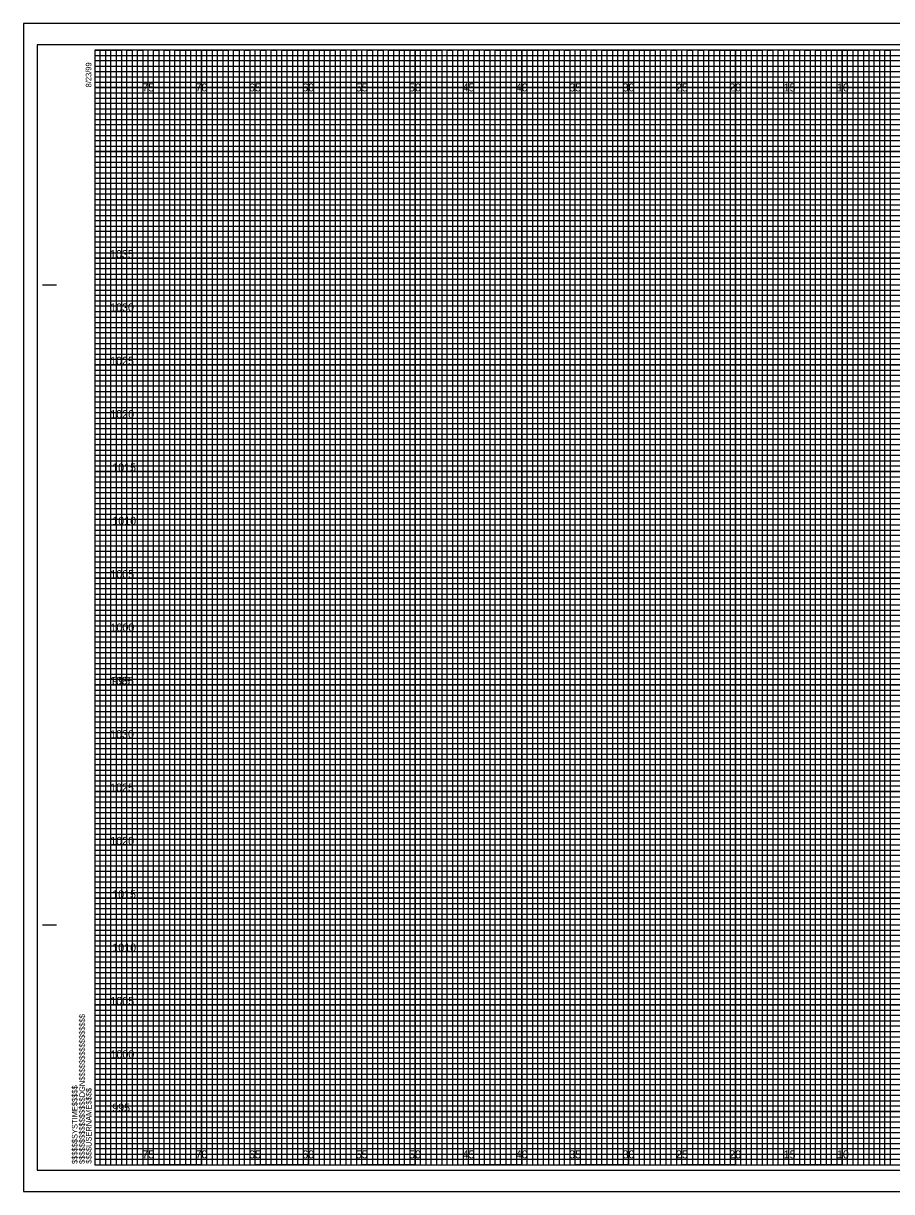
# Model space of a CAD drawing. Extents: x -7 to 162, y -2 to 987.
# Drawn here: x -6.7 to 74.6, y 437.5 to 547 of the extents above; entities that cross this region are included whole.
import ezdxf

# ---------------------------------------------------------------- set-up
doc = ezdxf.new("R2010")
doc.units = 0
for name, color, linetype in [('Exist Cross Section Cell', 7, 'Continuous'), ('Exist XS Center Line Elevation Label', 7, 'Continuous'), ('Exist XS Ground Line', 7, 'Continuous'), ('Prop CMT Concrete Structures', 7, 'Continuous'), ('Prop CMT Guardrail Widen Shoulder', 7, 'Continuous'), ('Prop CMT Pvmt Course 1', 7, 'Continuous'), ('Prop CMT Pvmt Surface', 7, 'Continuous'), ('Prop CMT Shld Paved Course 1', 7, 'Continuous'), ('Prop CMT Slope Grass', 7, 'Continuous'), ('Prop CMT Subgrade Earthwork', 7, 'Continuous'), ('Typical Text Label CELL', 7, 'Continuous')]:
    doc.layers.add(name, color=color, linetype=linetype)

msp = doc.modelspace()

# ---------------------------------------------------------------- linework, layer by layer
at = {"layer": 'Exist XS Center Line Elevation Label'}
for points in [[(0, 544.5), (2.5, 544.5), (2.5, 440), (7.5, 440), (7.5, 544.5), (12.5, 544.5), (12.5, 440), (17.5, 440), (17.5, 544.5), (22.5, 544.5), (22.5, 440), (27.5, 440), (27.5, 544.5), (32.5, 544.5), (32.5, 440), (37.5, 440), (37.5, 544.5), (42.5, 544.5), (42.5, 440), (47.5, 440), (47.5, 544.5), (52.5, 544.5), (52.5, 440), (57.5, 440), (57.5, 544.5), (62.5, 544.5), (62.5, 440), (67.5, 440), (67.5, 544.5), (72.5, 544.5), (72.5, 440), (77.5, 440)], [(0, 542), (137.5, 542)], [(0, 532.5), (160, 532.5), (160, 537.5), (0, 537.5)], [(0, 522.5), (160, 522.5), (160, 527.5), (0, 527.5)], [(0, 512.5), (160, 512.5), (160, 517.5), (0, 517.5)], [(0, 502.5), (160, 502.5), (160, 507.5), (0, 507.5)], [(0, 492.5), (160, 492.5), (160, 497.5), (0, 497.5)], [(0, 482.5), (160, 482.5), (160, 487.5), (0, 487.5)], [(0, 472.5), (160, 472.5), (160, 477.5), (0, 477.5)], [(0, 462.5), (160, 462.5), (160, 467.5), (0, 467.5)], [(0, 452.5), (160, 452.5), (160, 457.5), (0, 457.5)], [(0, 442.5), (160, 442.5), (160, 447.5), (0, 447.5)]]:
    msp.add_lwpolyline(points, dxfattribs=at)
at = {"layer": 'Exist XS Ground Line'}
for p, q in [((5, 544.5), (0, 544.5)), ((5, 440), (5, 544.5)), ((15, 544.5), (10, 544.5)), ((10, 544.5), (10, 440)), ((15, 440), (15, 544.5)), ((25, 544.5), (20, 544.5)), ((20, 544.5), (20, 440)), ((25, 440), (25, 544.5)), ((35, 544.5), (30, 544.5)), ((30, 544.5), (30, 440)), ((35, 440), (35, 544.5)), ((45, 544.5), (40, 544.5)), ((40, 544.5), (40, 440)), ((45, 440), (45, 544.5)), ((55, 544.5), (50, 544.5)), ((50, 544.5), (50, 440)), ((55, 440), (55, 544.5)), ((65, 544.5), (60, 544.5)), ((60, 544.5), (60, 440)), ((65, 440), (65, 544.5)), ((75, 544.5), (70, 544.5)), ((70, 544.5), (70, 440)), ((10, 440), (5, 440)), ((20, 440), (15, 440)), ((30, 440), (25, 440)), ((40, 440), (35, 440)), ((50, 440), (45, 440)), ((60, 440), (55, 440)), ((70, 440), (65, 440))]:
    msp.add_line(p, q, dxfattribs=at)
for points in [[(0, 540), (160, 540), (160, 535), (0, 535)], [(0, 530), (160, 530), (160, 525), (0, 525)], [(0, 520), (160, 520), (160, 515), (0, 515)], [(0, 510), (160, 510), (160, 505), (0, 505)], [(0, 500), (160, 500), (160, 495), (0, 495)], [(0, 490), (160, 490), (160, 485), (0, 485)], [(0, 480), (160, 480), (160, 475), (0, 475)], [(0, 470), (160, 470), (160, 465), (0, 465)], [(0, 460), (160, 460), (160, 455), (0, 455)], [(0, 450), (160, 450), (160, 445), (0, 445)]]:
    msp.add_lwpolyline(points, dxfattribs=at)
at = {"layer": 'Prop CMT Concrete Structures'}
for p, q in [((5, 440), (5, 544.5)), ((10, 440), (10, 544.5)), ((15, 440), (15, 544.5)), ((20, 440), (20, 544.5)), ((25, 440), (25, 544.5)), ((30, 440), (30, 544.5)), ((35, 440), (35, 544.5)), ((40, 440), (40, 544.5)), ((45, 440), (45, 544.5)), ((50, 440), (50, 544.5)), ((55, 440), (55, 544.5)), ((60, 440), (60, 544.5)), ((65, 440), (65, 544.5)), ((70, 440), (70, 544.5)), ((0, 540), (160, 540)), ((0, 535), (160, 535)), ((0, 530), (160, 530)), ((0, 525), (160, 525)), ((0, 520), (160, 520)), ((0, 515), (160, 515)), ((0, 510), (160, 510)), ((0, 505), (160, 505)), ((0, 500), (160, 500)), ((0, 495), (160, 495)), ((0, 490), (160, 490)), ((0, 485), (160, 485)), ((0, 480), (160, 480)), ((0, 475), (160, 475)), ((0, 470), (160, 470)), ((0, 465), (160, 465)), ((0, 460), (160, 460)), ((0, 455), (160, 455)), ((0, 450), (160, 450)), ((0, 445), (160, 445))]:
    msp.add_line(p, q, dxfattribs=at)
at = {"layer": 'Prop CMT Guardrail Widen Shoulder'}
for p, q in [((161.65, 547), (-6.7, 547)), ((-6.7, 547), (-6.7, 437.5)), ((-6.7, 437.5), (161.65, 437.5))]:
    msp.add_line(p, q, dxfattribs=at)
at = {"layer": 'Prop CMT Pvmt Course 1'}
msp.add_lwpolyline([(-6.7, 437.5), (161.65, 437.5), (161.65, 547), (-6.7, 547)], close=True, dxfattribs=at)
at = {"layer": 'Prop CMT Pvmt Surface'}
for points in [[(0, 440), (0.5, 440), (0.5, 544.5), (1, 544.5), (1, 440)], [(1, 440), (1.5, 440), (1.5, 544.5), (2, 544.5), (2, 440)], [(2.5, 440), (3, 440), (3, 544.5), (3.5, 544.5), (3.5, 440)], [(3.5, 440), (4, 440), (4, 544.5), (4.5, 544.5), (4.5, 440)], [(5, 440), (5.5, 440), (5.5, 544.5), (6, 544.5), (6, 440)], [(6, 440), (6.5, 440), (6.5, 544.5), (7, 544.5), (7, 440)], [(7.5, 440), (8, 440), (8, 544.5), (8.5, 544.5), (8.5, 440)], [(8.5, 440), (9, 440), (9, 544.5), (9.5, 544.5), (9.5, 440)], [(10, 440), (10.5, 440), (10.5, 544.5), (11, 544.5), (11, 440)], [(11, 440), (11.5, 440), (11.5, 544.5), (12, 544.5), (12, 440)], [(12.5, 440), (13, 440), (13, 544.5), (13.5, 544.5), (13.5, 440)], [(13.5, 440), (14, 440), (14, 544.5), (14.5, 544.5), (14.5, 440)], [(15, 440), (15.5, 440), (15.5, 544.5), (16, 544.5), (16, 440)], [(16, 440), (16.5, 440), (16.5, 544.5), (17, 544.5), (17, 440)], [(17.5, 440), (18, 440), (18, 544.5), (18.5, 544.5), (18.5, 440)], [(18.5, 440), (19, 440), (19, 544.5), (19.5, 544.5), (19.5, 440)], [(20, 440), (20.5, 440), (20.5, 544.5), (21, 544.5), (21, 440)], [(21, 440), (21.5, 440), (21.5, 544.5), (22, 544.5), (22, 440)], [(22.5, 440), (23, 440), (23, 544.5), (23.5, 544.5), (23.5, 440)], [(23.5, 440), (24, 440), (24, 544.5), (24.5, 544.5), (24.5, 440)], [(25, 440), (25.5, 440), (25.5, 544.5), (26, 544.5), (26, 440)], [(26, 440), (26.5, 440), (26.5, 544.5), (27, 544.5), (27, 440)], [(27.5, 440), (28, 440), (28, 544.5), (28.5, 544.5), (28.5, 440)], [(28.5, 440), (29, 440), (29, 544.5), (29.5, 544.5), (29.5, 440)], [(30, 440), (30.5, 440), (30.5, 544.5), (31, 544.5), (31, 440)], [(31, 440), (31.5, 440), (31.5, 544.5), (32, 544.5), (32, 440)], [(32.5, 440), (33, 440), (33, 544.5), (33.5, 544.5), (33.5, 440)], [(33.5, 440), (34, 440), (34, 544.5), (34.5, 544.5), (34.5, 440)], [(35, 440), (35.5, 440), (35.5, 544.5), (36, 544.5), (36, 440)], [(36, 440), (36.5, 440), (36.5, 544.5), (37, 544.5), (37, 440)], [(37.5, 440), (38, 440), (38, 544.5), (38.5, 544.5), (38.5, 440)], [(38.5, 440), (39, 440), (39, 544.5), (39.5, 544.5), (39.5, 440)], [(40, 440), (40.5, 440), (40.5, 544.5), (41, 544.5), (41, 440)], [(41, 440), (41.5, 440), (41.5, 544.5), (42, 544.5), (42, 440)], [(42.5, 440), (43, 440), (43, 544.5), (43.5, 544.5), (43.5, 440)], [(43.5, 440), (44, 440), (44, 544.5), (44.5, 544.5), (44.5, 440)], [(45, 440), (45.5, 440), (45.5, 544.5), (46, 544.5), (46, 440)], [(46, 440), (46.5, 440), (46.5, 544.5), (47, 544.5), (47, 440)], [(47.5, 440), (48, 440), (48, 544.5), (48.5, 544.5), (48.5, 440)], [(48.5, 440), (49, 440), (49, 544.5), (49.5, 544.5), (49.5, 440)], [(50, 440), (50.5, 440), (50.5, 544.5), (51, 544.5), (51, 440)], [(51, 440), (51.5, 440), (51.5, 544.5), (52, 544.5), (52, 440)], [(52.5, 440), (53, 440), (53, 544.5), (53.5, 544.5), (53.5, 440)], [(53.5, 440), (54, 440), (54, 544.5), (54.5, 544.5), (54.5, 440)], [(55, 440), (55.5, 440), (55.5, 544.5), (56, 544.5), (56, 440)], [(56, 440), (56.5, 440), (56.5, 544.5), (57, 544.5), (57, 440)], [(57.5, 440), (58, 440), (58, 544.5), (58.5, 544.5), (58.5, 440)], [(58.5, 440), (59, 440), (59, 544.5), (59.5, 544.5), (59.5, 440)], [(60, 440), (60.5, 440), (60.5, 544.5), (61, 544.5), (61, 440)], [(61, 440), (61.5, 440), (61.5, 544.5), (62, 544.5), (62, 440)], [(62.5, 440), (63, 440), (63, 544.5), (63.5, 544.5), (63.5, 440)], [(63.5, 440), (64, 440), (64, 544.5), (64.5, 544.5), (64.5, 440)], [(65, 440), (65.5, 440), (65.5, 544.5), (66, 544.5), (66, 440)], [(66, 440), (66.5, 440), (66.5, 544.5), (67, 544.5), (67, 440)], [(67.5, 440), (68, 440), (68, 544.5), (68.5, 544.5), (68.5, 440)], [(68.5, 440), (69, 440), (69, 544.5), (69.5, 544.5), (69.5, 440)], [(70, 440), (70.5, 440), (70.5, 544.5), (71, 544.5), (71, 440)], [(71, 440), (71.5, 440), (71.5, 544.5), (72, 544.5), (72, 440)], [(72.5, 440), (73, 440), (73, 544.5), (73.5, 544.5), (73.5, 440)], [(73.5, 440), (74, 440), (74, 544.5), (74.5, 544.5), (74.5, 440)]]:
    msp.add_lwpolyline(points, dxfattribs=at)
at = {"layer": 'Prop CMT Shld Paved Course 1'}
for p, q in [((0, 544), (130, 544)), ((130, 543.49), (0, 543.49)), ((0, 543.49), (0, 543)), ((0, 543), (130, 543)), ((130, 542.45), (0, 542.45)), ((0, 542.45), (0, 541.5)), ((0, 541.5), (160, 541.5))]:
    msp.add_line(p, q, dxfattribs=at)
for points in [[(0, 541), (135, 541), (160, 541), (160, 541), (0, 541)], [(0, 540.5), (160, 540.5), (160, 539.5), (0, 539.5)], [(0, 539), (160, 539), (160, 538.5), (0, 538.49)], [(0, 538), (160, 538), (160, 537), (0, 537)], [(0, 536.5), (160, 536.5), (160, 536), (0, 536)], [(0, 535.5), (160, 535.5), (160, 534.5), (0, 534.5)], [(0, 534), (160, 534), (160, 533.5), (0, 533.5)], [(0, 533), (160, 533), (160, 532), (0, 532)], [(0, 531.5), (160, 531.5), (160, 531), (0, 531)], [(0, 530.5), (160, 530.5), (160, 529.5), (0, 529.5)], [(0, 529), (160, 529), (160, 528.5), (0, 528.5)], [(0, 528), (160, 528), (160, 526.98), (160, 526.5), (160, 526), (0, 526)], [(0, 527), (160, 527), (160, 526.5), (0, 526.5)], [(0, 525.5), (160, 525.5), (160, 524.5), (0, 524.51)], [(0, 524.51), (160, 524.5), (160, 524), (0, 524)], [(0, 523.5), (160, 523.5), (160, 523), (0, 523)], [(0, 522), (160, 522), (160, 521.5), (0, 521.5)], [(0, 521), (160, 521), (160, 520.5), (0, 520.5)], [(-0.04, 519.45), (160, 519.45), (160, 518.94), (-0.04, 518.94)], [(0, 518.5), (160, 518.5), (160, 518), (0, 518)], [(0, 517), (160, 517), (160, 516.5), (0, 516.5)], [(0, 516), (160, 516), (160, 515.5), (0, 515.5)], [(0, 514.5), (160, 514.5), (160, 514), (0, 514)], [(0, 513.5), (160, 513.5), (160, 513), (0, 513)], [(0, 512), (160, 512), (160, 511.5), (0, 511.5)], [(0, 511), (160, 511), (160, 510.5), (0, 510.5)], [(0, 509.5), (160, 509.5), (160, 508.99), (0, 509)], [(0, 508.5), (160, 508.5), (160, 508), (0, 508)], [(0, 507), (160, 507), (160, 506.5), (0, 506.5)], [(0, 506), (160, 506), (160, 505.5), (0, 505.5)], [(0, 504.5), (160, 504.5), (160, 504), (0, 504)], [(0, 503.5), (160, 503.5), (160, 503), (0, 503)], [(0, 502), (160, 502), (160, 501.5), (0, 501.5)], [(0, 501), (160, 501), (160, 500.5), (0, 500.5)], [(0, 499.5), (160, 499.5), (160, 499), (0, 499)], [(0, 498.5), (160.03, 498.45), (160, 498), (0, 498)], [(0, 497), (160, 497), (160, 496.5), (0, 496.5)], [(0, 496), (160, 496), (160, 495.5), (0, 495.5)], [(0, 494.5), (160, 494.5), (160, 494), (0, 494)], [(0, 493.5), (160, 493.5), (160, 493), (0, 493)], [(0, 492), (160, 492), (160, 491.5), (0, 491.5)], [(0, 491), (160, 491), (160, 490.5), (0, 490.5)], [(0, 489.5), (160, 489.5), (160, 489), (0, 489)], [(0, 488.5), (160, 488.5), (160, 488), (0, 488)], [(0, 487), (160, 487), (160, 486.5), (0, 486.5)], [(0, 486), (160, 486), (160, 485.5), (0, 485.5)], [(0, 484.5), (160, 484.5), (160, 484), (0, 484)], [(0, 483.5), (160, 483.5), (160, 483), (0, 483)], [(0, 482), (160, 482), (160, 481.5), (0, 481.5)], [(0, 481), (160, 481), (160, 480.5), (0, 480.5)], [(0, 479.5), (160, 479.5), (160, 478.99), (0, 479)], [(0, 478.5), (160, 478.5), (160, 478), (0, 478)], [(0, 477), (160, 477), (160, 476.5), (0, 476.5)], [(0, 476), (160, 476), (160, 475.5), (0, 475.5)], [(0, 474.5), (160, 474.5), (160, 474), (0, 474)], [(0, 473.5), (160, 473.5), (160, 473), (0, 473)], [(0, 472), (160, 472), (160, 471.5), (0, 471.5)], [(0, 471), (160, 471), (160, 470.5), (0, 470.5)], [(0, 469.5), (160, 469.5), (160, 469), (0, 469)], [(0, 468.5), (160.03, 468.45), (160, 468), (0, 468)], [(0, 467), (160, 467), (160, 466.5), (0, 466.5)], [(0, 466), (160, 466), (160, 465.5), (0, 465.5)], [(0, 464.5), (160, 464.5), (160, 464), (0, 464)], [(0, 463.5), (160, 463.5), (160, 463), (0, 463)], [(0, 462), (160, 462), (160, 461.5), (0, 461.5)], [(0, 461), (160, 461), (160, 460.5), (0, 460.5)], [(0, 459.5), (160, 459.5), (160, 459), (0, 459)], [(0, 458.5), (160, 458.5), (160, 458), (0, 458)], [(0, 457), (160, 457), (160, 456.5), (0, 456.5)], [(0, 456), (160, 456), (160, 455.5), (0, 455.5)], [(0, 454.5), (160, 454.5), (160, 454), (0, 454)], [(0, 453.5), (160, 453.5), (160, 453), (0, 453)], [(0, 452), (160, 452), (160, 451.5), (0, 451.5)], [(0, 451), (160, 451), (160, 450.5), (0, 450.5)], [(0, 449.5), (160, 449.5), (160, 449), (0, 449)], [(0, 448.5), (160, 448.5), (160, 448), (0, 448)], [(0, 447), (160, 447), (160, 446.5), (0, 446.5)], [(0, 446), (160, 446), (160, 445.5), (0, 445.5)], [(0, 444.5), (160, 444.5), (160, 444), (0, 444)], [(0, 443.5), (160, 443.5), (160, 443), (0, 443)], [(0, 442), (160, 442), (160, 441.5), (0, 441.5)], [(0, 441), (160, 441), (160, 440.5), (0, 440.5)]]:
    msp.add_lwpolyline(points, dxfattribs=at)
at = {"layer": 'Prop CMT Slope Grass'}
msp.add_lwpolyline([(-5.4, 439.5), (161.2, 439.5), (161.2, 545), (-5.4, 545)], close=True, dxfattribs=at)
at = {"layer": 'Prop CMT Subgrade Earthwork'}
for p, q in [((-4.9, 522.5), (-3.65, 522.5)), ((-4.85, 522.5), (-3.6, 522.5)), ((-4.9, 462.5), (-3.65, 462.5)), ((-4.85, 462.5), (-3.6, 462.5)), ((0, 440), (0, 440)), ((0, 440), (0, 440)), ((0, 440), (0, 440)), ((0, 440), (0, 440)), ((0, 440), (0, 440)), ((0, 440), (0, 440)), ((0, 440), (0, 440))]:
    msp.add_line(p, q, dxfattribs=at)
msp.add_lwpolyline([(160, 544.5), (0, 544.5), (0, 440), (160, 440)], close=True, dxfattribs=at)

# ---------------------------------------------------------------- texts
at = {"layer": 'Exist Cross Section Cell'}
for s, p in [('75', (4.44, 540.62)), ('70', (9.43, 540.62)), ('65', (14.44, 540.62)), ('60', (19.43, 540.62)), ('55', (24.44, 540.62)), ('50', (29.43, 540.62)), ('45', (34.44, 540.62)), ('40', (39.43, 540.62)), ('35', (44.44, 540.62)), ('30', (49.43, 540.62)), ('25', (54.44, 540.62)), ('20', (59.43, 540.62)), ('15', (64.53, 540.62)), ('10', (69.52, 540.62)), ('75', (4.44, 440.62)), ('70', (9.43, 440.62)), ('65', (14.44, 440.62)), ('60', (19.43, 440.62)), ('55', (24.44, 440.62)), ('50', (29.43, 440.62)), ('45', (34.44, 440.62)), ('40', (39.43, 440.62)), ('35', (44.44, 440.62)), ('30', (49.43, 440.62)), ('25', (54.44, 440.62)), ('20', (59.43, 440.62)), ('15', (64.53, 440.62)), ('10', (69.52, 440.62))]:
    msp.add_text(s, height=0.75, dxfattribs=at).set_placement(p)
at = {"layer": 'Prop CMT Subgrade Earthwork'}
for s, p in [('8/23/99', (-0.33, 541)), ('$$$$$$$$$$$$$$$$DGN$$$$$$$$$$$$$$$$', (-0.94, 440.09)), ('$$$$$$SYSTIME$$$$$', (-1.63, 440.09)), ('$$$$USERNAME$$$$', (-0.31, 440.12))]:
    msp.add_text(s, height=0.525, rotation=90, dxfattribs=at).set_placement(p)
at = {"layer": 'Typical Text Label CELL'}
for s, p in [('1035', (1.42, 525)), ('1030', (1.43, 520)), ('1025', (1.43, 515)), ('1020', (1.44, 510)), ('1015', (1.62, 505)), ('1010', (1.63, 500)), ('1005', (1.45, 495)), ('1000', (1.46, 490)), ('1035', (1.42, 485)), ('995', (1.62, 485)), ('1030', (1.43, 480)), ('1025', (1.43, 475)), ('1020', (1.44, 470)), ('1015', (1.62, 465)), ('1010', (1.63, 460)), ('1005', (1.45, 455)), ('1000', (1.46, 450)), ('995', (1.62, 445))]:
    msp.add_text(s, height=0.75, dxfattribs=at).set_placement(p)

doc.saveas('drawing.dxf')
